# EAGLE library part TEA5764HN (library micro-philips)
FM radio + RDS single chip electronically tuned FM stereo radio with Radio Data System (RDS) and Radio Broadcast Data System (RBDS) demodulator and RDS/RBDS decoder for portable application with fully integrated IF selectivity and demodulation. Source: http://www.nxp.com .. TEA5764HN_2.pdf
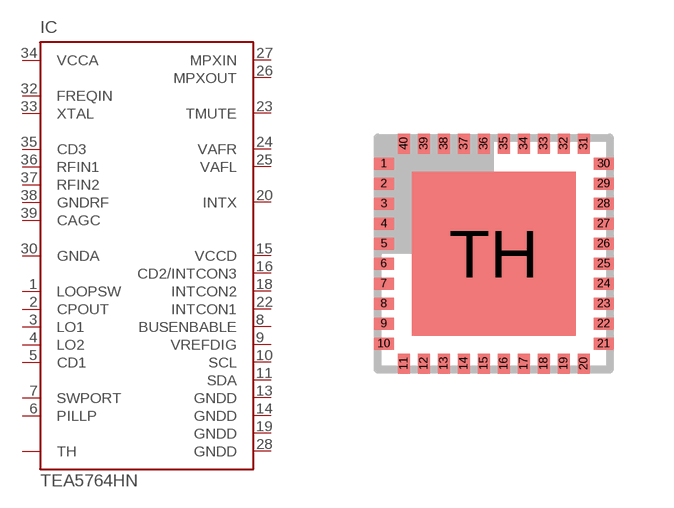
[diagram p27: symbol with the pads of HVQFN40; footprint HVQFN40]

Designator prefix IC

## TEA5764HN (OC_FARNELL: unknown; OC_NEWARK: unknown)  [HVQFN40]
1  LOOPSW  in
2  CPOUT  in
3  LO1  in
4  LO2  in
5  CD1  in
6  PILLP  in
7  SWPORT  out
8  BUSENBABLE  in
9  VREFDIG  in
10  SCL  in
11  SDA
13  GNDD  pwr
14  GNDD  pwr
15  VCCD  pwr
16  CD2/INTCON3  in
18  INTCON2  in
19  GNDD  pwr
20  INTX  out
22  INTCON1  in
23  TMUTE  in
24  VAFR  out
25  VAFL  out
26  MPXOUT  out
27  MPXIN  in
28  GNDD  pwr
30  GNDA  in
32  FREQIN  in
33  XTAL  in
34  VCCA  in
35  CD3  in
36  RFIN1  in
37  RFIN2  in
38  GNDRF  in
39  CAGC  in
TH  TH  pas

## Footprint HVQFN40 (pad centres in mm)
HVQFN40 plastic thermal enhanced very thin quad flat package SOT618-1 no leads; 40 terminals; body 6 x 6 x 0.85 mm Source: http://www.semiconductors.philips.com/acrobat_download/packages/SOT618-1.pdf
smd 0.5 x 0.3: 1 -2.75,2.25; 2 -2.75,1.75; 3 -2.75,1.25; 4 -2.75,0.75; 5 -2.75,0.25; 6 -2.75,-0.25; 7 -2.75,-0.75; 8 -2.75,-1.25; 9 -2.75,-1.75; 10 -2.75,-2.25; 21 2.75,-2.25; 22 2.75,-1.75; 23 2.75,-1.25; 24 2.75,-0.75; 25 2.75,-0.25; 26 2.75,0.25; 27 2.75,0.75; 28 2.75,1.25; 29 2.75,1.75; 30 2.75,2.25
smd 0.3 x 0.5: 11 -2.25,-2.75; 12 -1.75,-2.75; 13 -1.25,-2.75; 14 -0.75,-2.75; 15 -0.25,-2.75; 16 0.25,-2.75; 17 0.75,-2.75; 18 1.25,-2.75; 19 1.75,-2.75; 20 2.25,-2.75; 31 2.25,2.75; 32 1.75,2.75; 33 1.25,2.75; 34 0.75,2.75; 35 0.25,2.75; 36 -0.25,2.75; 37 -0.75,2.75; 38 -1.25,2.75; 39 -1.75,2.75; 40 -2.25,2.75
smd 4.1 x 4.1: TH 0,0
